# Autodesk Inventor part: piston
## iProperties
Shininess: 64.0
Length Units: 11269
Angle Units: 11279
Time Units: 11290
Mass Units: 11283
Length Display Precision: 3
Angle Display Precision: 2
Compacted: True
Part Number: piston
Document SubType Name: Modeling
Created: 2005-01
Material: Par défaut
Designer: David
Manufacturer: Standard
Standards Organization: Custom
Density: 0.0
Volumn: 0.0
Area: 0.0
PropertySet Name: Model Information
Control State: 0
Master: False
Checked Out: False
Author: David
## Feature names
1. Révolution1 [Revolution]
2. Chanfrein1 [Chamfer]
3. Chanfrein2 [Chamfer]
